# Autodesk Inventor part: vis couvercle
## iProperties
Created: 2002-03
Part Number: vis couvercle
Material: Par défaut
Document SubType Name: Modélisation
Designer: User
Control State: 0
Master: False
Checked Out: False
Shininess: 20.0
Length Units: 11269
Angle Units: 11279
Time Units: 11290
Mass Units: 11283
Length Display Precision: 3
Angle Display Precision: 2
Density: 0.0
Volumn: 0.0
Area: 0.0
PropertySet Name: Model Information
Author: User
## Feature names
1. Extrusion1
2. Extrusion2
3. Chanfrein1 [Chamfer]
4. Extrusion3
5. Congé1 [Fillet]
